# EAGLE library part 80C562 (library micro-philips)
8051-compatible 8bit Microcontroller
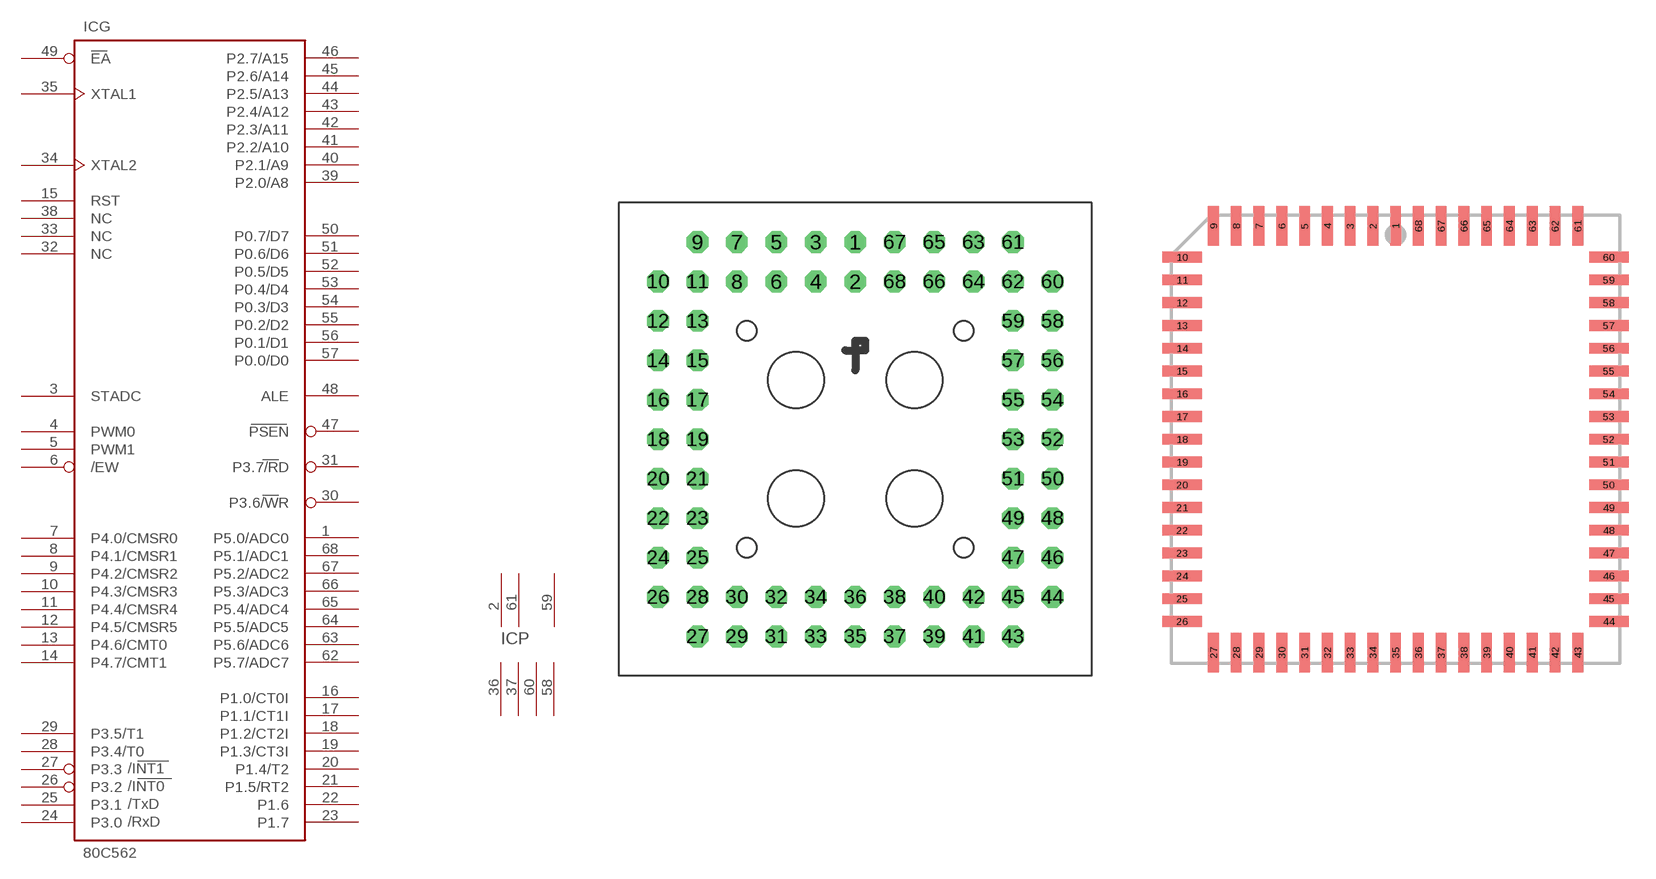
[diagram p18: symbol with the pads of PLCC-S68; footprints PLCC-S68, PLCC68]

Designator prefix IC; gates P=PWR5+2 G=8XC562

## 80C562 (MPN: P80C562EBA/02,512; OC_FARNELL: 121198; OC_NEWARK: 70R8452)  [PLCC-S68]
1  G:P5.0/ADC0
2  P:VDD  pwr
3  G:STADC
4  G:PWM0
5  G:PWM1
6  G:/EW
7  G:P4.0/CMSR0
8  G:P4.1/CMSR1
9  G:P4.2/CMSR2
10  G:P4.3/CMSR3
11  G:P4.4/CMSR4
12  G:P4.5/CMSR5
13  G:P4.6/CMT0
14  G:P4.7/CMT1
15  G:RST  in
16  G:P1.0/CT0I
17  G:P1.1/CT1I
18  G:P1.2/CT2I
19  G:P1.3/CT3I
20  G:P1.4/T2
21  G:P1.5/RT2
22  G:P1.6
23  G:P1.7
24  G:P3.0
25  G:P3.1
26  G:P3.2
27  G:P3.3
28  G:P3.4/T0
29  G:P3.5/T1
30  G:P3.6/WR
31  G:P3.7/RD
32  G:NC  nc
33  G:NC  nc
34  G:XTAL2  in
35  G:XTAL1  in
36  P:VSS  pwr
37  P:VSS  pwr
38  G:NC  nc
39  G:P2.0/A8  out
40  G:P2.1/A9  out
41  G:P2.2/A10  out
42  G:P2.3/A11  out
43  G:P2.4/A12  out
44  G:P2.5/A13  out
45  G:P2.6/A14  out
46  G:P2.7/A15  out
47  G:PSEN  out
48  G:ALE  out
49  G:EA  in
50  G:P0.7/D7
51  G:P0.6/D6
52  G:P0.5/D5
53  G:P0.4/D4
54  G:P0.3/D3
55  G:P0.2/D2
56  G:P0.1/D1
57  G:P0.0/D0
58  P:AVREF-  pwr
59  P:VREF  pwr
60  P:AVSS  pwr
61  P:AVDD  pwr
62  G:P5.7/ADC7
63  G:P5.6/ADC6
64  G:P5.5/ADC5
65  G:P5.4/ADC4
66  G:P5.3/ADC3
67  G:P5.2/ADC2
68  G:P5.1/ADC1

## 80C562SMD (OC_FARNELL: unknown; OC_NEWARK: unknown)  [PLCC68]
Pads as for PLCC-S68

## Footprint PLCC-S68 (pad centres in mm)
PLASTIC LEADED CHIP CARRIER Socked
drill 0.813 pad 1.397 octagon: 1 0,12.7; 2 0,10.16; 3 -2.54,12.7; 4 -2.54,10.16; 5 -5.08,12.7; 6 -5.08,10.16; 7 -7.62,12.7; 8 -7.62,10.16; 9 -10.16,12.7; 10 -12.7,10.16; 11 -10.16,10.16; 12 -12.7,7.62; 13 -10.16,7.62; 14 -12.7,5.08; 15 -10.16,5.08; 16 -12.7,2.54; 17 -10.16,2.54; 18 -12.7,0; 19 -10.16,0; 20 -12.7,-2.54; 21 -10.16,-2.54; 22 -12.7,-5.08; 23 -10.16,-5.08; 24 -12.7,-7.62; 25 -10.16,-7.62; 26 -12.7,-10.16; 27 -10.16,-12.7; 28 -10.16,-10.16; 29 -7.62,-12.7; 30 -7.62,-10.16; 31 -5.08,-12.7; 32 -5.08,-10.16; 33 -2.54,-12.7; 34 -2.54,-10.16; 35 0,-12.7; 36 0,-10.16; 37 2.54,-12.7; 38 2.54,-10.16; 39 5.08,-12.7; 40 5.08,-10.16; 41 7.62,-12.7; 42 7.62,-10.16; 43 10.16,-12.7; 44 12.7,-10.16; 45 10.16,-10.16; 46 12.7,-7.62; 47 10.16,-7.62; 48 12.7,-5.08; 49 10.16,-5.08; 50 12.7,-2.54; 51 10.16,-2.54; 52 12.7,0; 53 10.16,0; 54 12.7,2.54; 55 10.16,2.54; 56 12.7,5.08; 57 10.16,5.08; 58 12.7,7.62; 59 10.16,7.62; 60 12.7,10.16; 61 10.16,12.7; 62 10.16,10.16; 63 7.62,12.7; 64 7.62,10.16; 65 5.08,12.7; 66 5.08,10.16; 67 2.54,12.7; 68 2.54,10.16

## Footprint PLCC68 (pad centres in mm)
PLASTIC LEADED CHIP CARRIER square
smd 0.6 x 2.2: 1 0,11.9; 2 -1.27,11.9; 3 -2.54,11.9; 4 -3.81,11.9; 5 -5.08,11.9; 6 -6.35,11.9; 7 -7.62,11.9; 8 -8.89,11.9; 9 -10.16,11.9; 27 -10.16,-11.9; 28 -8.89,-11.9; 29 -7.62,-11.9; 30 -6.35,-11.9; 31 -5.08,-11.9; 32 -3.81,-11.9; 33 -2.54,-11.9; 34 -1.27,-11.9; 35 0,-11.9; 36 1.27,-11.9; 37 2.54,-11.9; 38 3.81,-11.9; 39 5.08,-11.9; 40 6.35,-11.9; 41 7.62,-11.9; 42 8.89,-11.9; 43 10.16,-11.9; 61 10.16,11.9; 62 8.89,11.9; 63 7.62,11.9; 64 6.35,11.9; 65 5.08,11.9; 66 3.81,11.9; 67 2.54,11.9; 68 1.27,11.9
smd 2.2 x 0.6: 10 -11.9,10.16; 11 -11.9,8.89; 12 -11.9,7.62; 13 -11.9,6.35; 14 -11.9,5.08; 15 -11.9,3.81; 16 -11.9,2.54; 17 -11.9,1.27; 18 -11.9,0; 19 -11.9,-1.27; 20 -11.9,-2.54; 21 -11.9,-3.81; 22 -11.9,-5.08; 23 -11.9,-6.35; 24 -11.9,-7.62; 25 -11.9,-8.89; 26 -11.9,-10.16; 44 11.9,-10.16; 45 11.9,-8.89; 46 11.9,-7.62; 47 11.9,-6.35; 48 11.9,-5.08; 49 11.9,-3.81; 50 11.9,-2.54; 51 11.9,-1.27; 52 11.9,0; 53 11.9,1.27; 54 11.9,2.54; 55 11.9,3.81; 56 11.9,5.08; 57 11.9,6.35; 58 11.9,7.62; 59 11.9,8.89; 60 11.9,10.16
